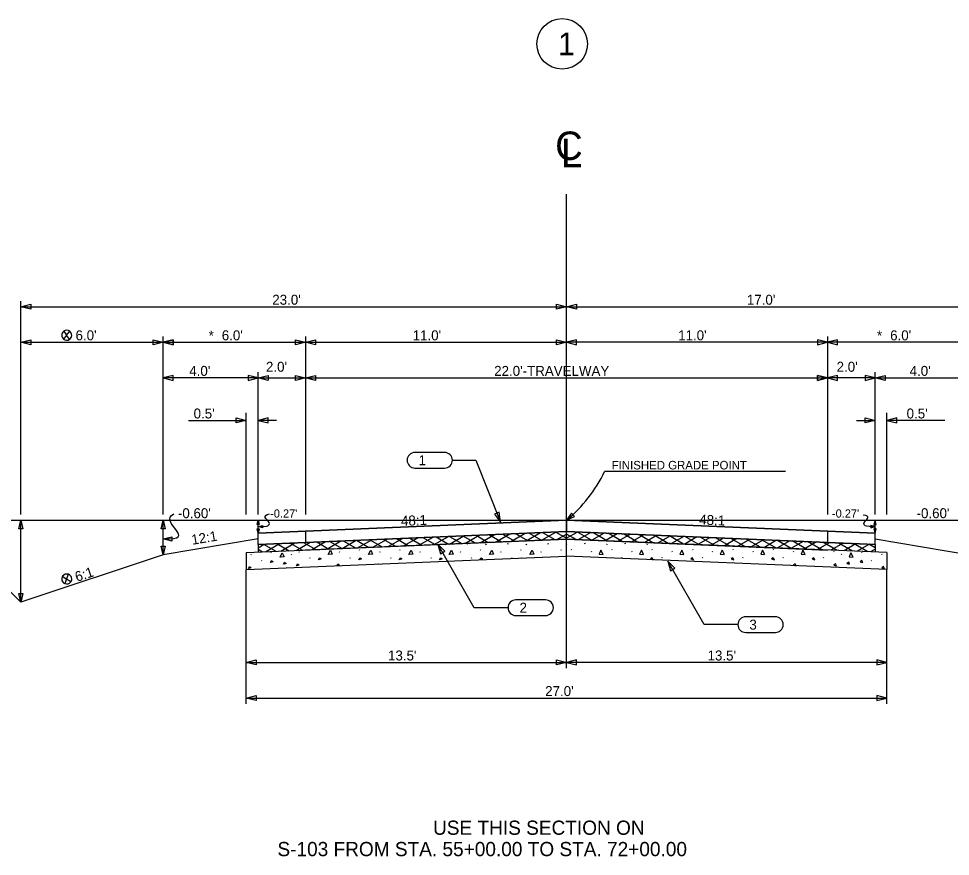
# Model space of a CAD drawing. Extents: x -859 to 797, y 1810 to 2851.
# Drawn here: x -418 to 236, y 2095 to 2684 of the extents above; entities that cross this region are included whole.
import ezdxf

# ---------------------------------------------------------------- set-up
doc = ezdxf.new("R2010")
doc.units = 0
doc.layers.add('Level 41', color=7, linetype='Continuous')

msp = doc.modelspace()

# ---------------------------------------------------------------- linework, layer by layer
at = {"layer": 'Level 41'}
for p, q in [((-33.31, 2227.73), (-33.31, 2560.73)), ((-416.65, 2335.73), (-416.65, 2485.73)), ((-416.65, 2481.73), (-33.31, 2481.73)), ((-33.31, 2481.73), (250.03, 2481.73)), ((-384.48, 2461.69), (-386.63, 2459)), ((-386.52, 2464.46), (-384.48, 2461.69)), ((-384.48, 2461.69), (-382.26, 2464.46)), ((-382.38, 2458.82), (-384.48, 2461.69)), ((-316.65, 2335.73), (-316.65, 2460.73)), ((-216.65, 2460.73), (-216.65, 2335.73)), ((150.03, 2460.73), (150.03, 2335.73)), ((-416.65, 2456.73), (-316.65, 2456.73)), ((-316.65, 2456.73), (-216.65, 2456.73)), ((-216.65, 2456.73), (-33.31, 2456.73)), ((150.03, 2456.73), (-33.31, 2456.73)), ((250.03, 2456.73), (150.03, 2456.73)), ((-249.98, 2335.73), (-249.98, 2435.73)), ((183.36, 2335.73), (183.36, 2435.73)), ((-249.98, 2431.73), (-316.65, 2431.73)), ((-249.98, 2431.73), (-216.65, 2431.73)), ((-216.65, 2431.73), (150.03, 2431.73)), ((183.36, 2431.73), (150.03, 2431.73)), ((183.36, 2431.73), (250.03, 2431.73)), ((-298.96, 2401.8), (-258.32, 2401.8)), ((-258.32, 2335.73), (-258.32, 2407.24)), ((-236.96, 2401.8), (-249.98, 2401.8)), ((170.34, 2401.8), (183.36, 2401.8)), ((191.7, 2335.73), (191.7, 2407.24)), ((232.35, 2401.8), (191.7, 2401.8)), ((-533.89, 2391.32), (-416.65, 2274.09)), ((-119.01, 2379.35), (-139.84, 2379.35)), ((-139.84, 2368.35), (-119.01, 2368.35)), ((120.47, 2365.88), (-6.65, 2365.88)), ((-554.3, 2331.73), (338.21, 2331.73)), ((-416.65, 2274.09), (-416.65, 2331.73)), ((-316.65, 2307.42), (-316.65, 2331.73)), ((-33.31, 2331.73), (-249.98, 2322.7)), ((-249.98, 2322.7), (-249.98, 2331.73)), ((-33.31, 2331.73), (-33.31, 2323.73)), ((-33.31, 2331.73), (183.36, 2322.7)), ((-33.31, 2331.73), (-33.31, 2323.73)), ((183.36, 2322.7), (183.36, 2331.73)), ((-249.98, 2314.7), (-33.3, 2323.73)), ((-216.63, 2324.1), (-216.63, 2316.09)), ((-50.84, 2317.66), (-40.89, 2323.41)), ((-40.94, 2323.41), (-33.31, 2319)), ((183.36, 2314.7), (-33.32, 2323.73)), ((-25.68, 2323.41), (-33.31, 2319)), ((-15.78, 2317.66), (-25.73, 2323.41)), ((150.01, 2324.1), (150.01, 2316.09)), ((-249.98, 2318.53), (-316.65, 2307.42)), ((-258.32, 2309.02), (-33.3, 2318.39)), ((-33.3, 2318.39), (-216.64, 2310.75)), ((-201.73, 2311.37), (-191.78, 2317.12)), ((-199.49, 2316.8), (-190.88, 2311.83)), ((-190.96, 2311.82), (-181, 2317.57)), ((-190.17, 2317.19), (-181.55, 2312.22)), ((-180.84, 2317.58), (-172.23, 2312.6)), ((-180.18, 2312.27), (-170.22, 2318.02)), ((-171.51, 2317.97), (-162.9, 2312.99)), ((-169.4, 2312.72), (-159.44, 2318.47)), ((-162.19, 2318.36), (-153.57, 2313.38)), ((-158.62, 2313.17), (-148.67, 2318.92)), ((-152.86, 2318.74), (-144.24, 2313.77)), ((-147.84, 2313.62), (-137.89, 2319.37)), ((-143.53, 2319.13), (-134.92, 2314.16)), ((-137.07, 2314.07), (-127.11, 2319.82)), ((-134.21, 2319.52), (-125.59, 2314.55)), ((-126.29, 2314.52), (-116.33, 2320.27)), ((-124.88, 2319.91), (-116.26, 2314.94)), ((-115.55, 2320.3), (-106.94, 2315.32)), ((-115.51, 2314.97), (-105.55, 2320.72)), ((-106.23, 2320.69), (-97.61, 2315.71)), ((-104.73, 2315.42), (-94.78, 2321.16)), ((-96.9, 2321.08), (-88.28, 2316.1)), ((-93.95, 2315.86), (-84, 2321.61)), ((-87.57, 2321.46), (-78.96, 2316.49)), ((-83.18, 2316.31), (-73.22, 2322.06)), ((-78.25, 2321.85), (-69.63, 2316.88)), ((-72.4, 2316.76), (-62.44, 2322.51)), ((-68.92, 2322.24), (-60.3, 2317.27)), ((-61.62, 2317.21), (-51.67, 2322.96)), ((-59.59, 2322.63), (-50.98, 2317.66)), ((-50.26, 2323.02), (-41.65, 2318.04)), ((-40.07, 2318.11), (-33.31, 2322.01)), ((191.7, 2309.02), (-33.32, 2318.39)), ((-33.32, 2318.39), (150.02, 2310.75)), ((-26.55, 2318.11), (-33.31, 2322.01)), ((-16.35, 2323.02), (-24.97, 2318.04)), ((-7.03, 2322.63), (-15.64, 2317.66)), ((-5, 2317.21), (-14.95, 2322.96)), ((2.3, 2322.24), (-6.32, 2317.27)), ((5.78, 2316.76), (-4.18, 2322.51)), ((11.63, 2321.85), (3.01, 2316.88)), ((16.56, 2316.31), (6.6, 2322.06)), ((20.95, 2321.46), (12.34, 2316.49)), ((27.34, 2315.86), (17.38, 2321.61)), ((30.28, 2321.08), (21.66, 2316.1)), ((38.11, 2315.42), (28.16, 2321.16)), ((39.61, 2320.69), (30.99, 2315.71)), ((48.89, 2314.97), (38.94, 2320.72)), ((48.93, 2320.3), (40.32, 2315.32)), ((58.26, 2319.91), (49.64, 2314.94)), ((59.67, 2314.52), (49.71, 2320.27)), ((67.59, 2319.52), (58.97, 2314.55)), ((70.45, 2314.07), (60.49, 2319.82)), ((76.91, 2319.13), (68.3, 2314.16)), ((81.22, 2313.62), (71.27, 2319.37)), ((86.24, 2318.74), (77.63, 2313.77)), ((92, 2313.17), (82.05, 2318.92)), ((95.57, 2318.36), (86.95, 2313.38)), ((102.78, 2312.72), (92.82, 2318.47)), ((104.9, 2317.97), (96.28, 2312.99)), ((113.56, 2312.27), (103.6, 2318.02)), ((114.22, 2317.58), (105.61, 2312.6)), ((124.34, 2311.82), (114.38, 2317.57)), ((123.55, 2317.19), (114.93, 2312.22)), ((132.88, 2316.8), (124.26, 2311.83)), ((135.11, 2311.37), (125.16, 2317.12)), ((183.36, 2318.53), (250.03, 2307.42)), ((-249.98, 2312.39), (-245.67, 2314.88)), ((-249.98, 2314.7), (-249.98, 2309.36)), ((-249.98, 2311.31), (-246.84, 2309.49)), ((-246.13, 2314.86), (-237.51, 2309.88)), ((-244.84, 2309.58), (-234.89, 2315.33)), ((-236.8, 2315.25), (-228.19, 2310.27)), ((-234.07, 2310.03), (-224.11, 2315.78)), ((-227.48, 2315.64), (-218.86, 2310.66)), ((-223.29, 2310.48), (-213.33, 2316.22)), ((-218.15, 2316.02), (-209.53, 2311.05)), ((-212.51, 2310.93), (-202.55, 2316.67)), ((-208.82, 2316.41), (-200.21, 2311.44)), ((-207.18, 2310.55), (-206.94, 2311.08)), ((-178.82, 2310.55), (-178.58, 2311.08)), ((-150.46, 2310.55), (-150.22, 2311.08)), ((-122.1, 2310.55), (-121.86, 2311.08)), ((-118.54, 2314.84), (-118.37, 2314.58)), ((-118.37, 2314.8), (-118.13, 2314.45)), ((-102.98, 2314.94), (-102.74, 2315.47)), ((-93.74, 2310.55), (-93.51, 2311.08)), ((-90.25, 2314.94), (-90.01, 2314.58)), ((-90.01, 2314.8), (-89.78, 2314.45)), ((-74.62, 2314.94), (-74.38, 2315.47)), ((-65.38, 2310.55), (-65.15, 2311.08)), ((-61.89, 2314.94), (-61.65, 2314.58)), ((-61.65, 2314.8), (-61.42, 2314.45)), ((-46.26, 2314.94), (-46.03, 2315.47)), ((-37.03, 2310.55), (-36.79, 2311.08)), ((-33.53, 2314.94), (-33.3, 2314.58)), ((-33.09, 2314.94), (-33.32, 2314.58)), ((-29.59, 2310.55), (-29.83, 2311.08)), ((-20.36, 2314.94), (-20.59, 2315.47)), ((-4.96, 2314.8), (-5.2, 2314.45)), ((-4.73, 2314.94), (-4.96, 2314.58)), ((-1.23, 2310.55), (-1.47, 2311.08)), ((8, 2314.94), (7.76, 2315.47)), ((23.39, 2314.8), (23.16, 2314.45)), ((23.63, 2314.94), (23.39, 2314.58)), ((27.12, 2310.55), (26.89, 2311.08)), ((36.36, 2314.94), (36.12, 2315.47)), ((51.75, 2314.8), (51.52, 2314.45)), ((51.93, 2314.84), (51.75, 2314.58)), ((55.48, 2310.55), (55.25, 2311.08)), ((83.84, 2310.55), (83.6, 2311.08)), ((112.2, 2310.55), (111.96, 2311.08)), ((142.2, 2316.41), (133.59, 2311.44)), ((145.89, 2310.93), (135.94, 2316.67)), ((140.56, 2310.55), (140.32, 2311.08)), ((151.53, 2316.02), (142.91, 2311.05)), ((156.67, 2310.48), (146.71, 2316.22)), ((160.86, 2315.64), (152.24, 2310.66)), ((167.45, 2310.03), (157.49, 2315.78)), ((170.18, 2315.25), (161.57, 2310.27)), ((178.23, 2309.58), (168.27, 2315.33)), ((179.51, 2314.86), (170.89, 2309.88)), ((183.36, 2312.39), (179.05, 2314.88)), ((183.36, 2311.31), (180.22, 2309.49)), ((183.36, 2314.7), (183.36, 2309.36)), ((-316.65, 2307.42), (-416.65, 2274.09)), ((-258.32, 2309.02), (-258.32, 2297.02)), ((-258.32, 2297.02), (-33.3, 2306.39)), ((-254.95, 2307.29), (-254.72, 2307.83)), ((-240.92, 2308.66), (-240.69, 2309.19)), ((-226.6, 2307.29), (-226.36, 2307.83)), ((-221.21, 2309.19), (-220.97, 2309.72)), ((-213.81, 2305.4), (-213.57, 2305.04)), ((-192.85, 2309.19), (-192.61, 2309.72)), ((-185.45, 2305.4), (-185.21, 2305.04)), ((-164.49, 2309.19), (-164.25, 2309.72)), ((-157.09, 2305.4), (-156.85, 2305.04)), ((-136.13, 2309.19), (-135.9, 2309.72)), ((-128.73, 2305.4), (-128.5, 2305.04)), ((-107.77, 2309.19), (-107.54, 2309.72)), ((-100.37, 2305.4), (-100.14, 2305.04)), ((-79.42, 2309.19), (-79.18, 2309.72)), ((-72.02, 2305.4), (-71.78, 2305.04)), ((-51.06, 2309.19), (-50.82, 2309.72)), ((191.7, 2297.02), (-33.32, 2306.39)), ((-15.56, 2309.19), (-15.8, 2309.72)), ((5.4, 2305.4), (5.16, 2305.04)), ((12.8, 2309.19), (12.56, 2309.72)), ((33.75, 2305.4), (33.52, 2305.04)), ((41.15, 2309.19), (40.92, 2309.72)), ((62.11, 2305.4), (61.88, 2305.04)), ((69.51, 2309.19), (69.28, 2309.72)), ((90.47, 2305.4), (90.23, 2305.04)), ((97.87, 2309.19), (97.63, 2309.72)), ((118.83, 2305.4), (118.59, 2305.04)), ((126.23, 2309.19), (125.99, 2309.72)), ((147.19, 2305.4), (146.95, 2305.04)), ((154.59, 2309.19), (154.35, 2309.72)), ((159.98, 2307.29), (159.74, 2307.83)), ((174.3, 2308.66), (174.07, 2309.19)), ((188.33, 2307.29), (188.1, 2307.83)), ((191.7, 2309.02), (191.7, 2297.02)), ((-247.55, 2303.5), (-247.32, 2303.15)), ((180.93, 2303.5), (180.7, 2303.15)), ((-387.29, 2292.33), (-384.48, 2290.35)), ((-384.48, 2290.35), (-383.25, 2293.68)), ((-258.32, 2202.73), (-258.32, 2297.02)), ((191.7, 2202.73), (191.7, 2297.02)), ((-384.48, 2290.35), (-385.67, 2287.12)), ((-381.58, 2288.3), (-384.48, 2290.35)), ((-48.12, 2275.72), (-68.96, 2275.72)), ((-68.96, 2264.72), (-48.12, 2264.72)), ((113.31, 2263.82), (92.48, 2263.82)), ((92.48, 2252.82), (113.31, 2252.82)), ((-258.32, 2231.73), (-33.31, 2231.73)), ((191.7, 2231.73), (-33.31, 2231.73)), ((-258.32, 2206.73), (191.7, 2206.73))]:
    msp.add_line(p, q, dxfattribs=at)
for points in [[(-409.65, 2479.98), (-416.65, 2481.73), (-409.65, 2483.48)], [(-40.31, 2483.48), (-33.31, 2481.73), (-40.31, 2479.98)], [(-26.31, 2479.98), (-33.31, 2481.73), (-26.31, 2483.48)], [(-409.65, 2454.98), (-416.65, 2456.73), (-409.65, 2458.48)], [(-323.65, 2458.48), (-316.65, 2456.73), (-323.65, 2454.98)], [(-309.65, 2458.48), (-316.65, 2456.73), (-309.65, 2454.98)], [(-309.65, 2454.98), (-316.65, 2456.73), (-309.65, 2458.48)], [(-223.65, 2458.48), (-216.65, 2456.73), (-223.65, 2454.98)], [(-209.65, 2454.98), (-216.65, 2456.73), (-209.65, 2458.48)], [(-40.31, 2458.48), (-33.31, 2456.73), (-40.31, 2454.98)], [(-26.31, 2458.48), (-33.31, 2456.73), (-26.31, 2454.98)], [(143.03, 2454.98), (150.03, 2456.73), (143.03, 2458.48)], [(157.03, 2458.48), (150.03, 2456.73), (157.03, 2454.98)], [(-309.65, 2433.48), (-316.65, 2431.73), (-309.65, 2429.98)], [(-256.98, 2429.98), (-249.98, 2431.73), (-256.98, 2433.48)], [(-242.98, 2429.98), (-249.98, 2431.73), (-242.98, 2433.48)], [(-223.65, 2433.48), (-216.65, 2431.73), (-223.65, 2429.98)], [(-209.65, 2429.98), (-216.65, 2431.73), (-209.65, 2433.48)], [(143.03, 2433.48), (150.03, 2431.73), (143.03, 2429.98)], [(143.03, 2429.98), (150.03, 2431.73), (143.03, 2433.48)], [(157.03, 2433.48), (150.03, 2431.73), (157.03, 2429.98)], [(176.36, 2429.98), (183.36, 2431.73), (176.36, 2433.48)], [(190.36, 2429.98), (183.36, 2431.73), (190.36, 2433.48)], [(-265.32, 2403.55), (-258.32, 2401.8), (-265.32, 2400.05)], [(-242.98, 2403.55), (-249.98, 2401.8), (-242.98, 2400.05)], [(176.36, 2403.55), (183.36, 2401.8), (176.36, 2400.05)], [(198.7, 2403.55), (191.7, 2401.8), (198.7, 2400.05)], [(-84.01, 2336.05), (-79.82, 2330.44), (-80.65, 2337.4)], [(-29.84, 2336.62), (-33.31, 2331.73), (-27.86, 2334.23)], [(-418.15, 2325.73), (-416.65, 2331.73), (-415.15, 2325.73)], [(-318.15, 2325.73), (-316.65, 2331.73), (-315.15, 2325.73)], [(-250.73, 2328.73), (-249.98, 2331.73), (-249.23, 2328.73)], [(-249.98, 2322.7), (-33.31, 2331.73), (-33.31, 2331.73), (-33.31, 2323.73), (-33.31, 2323.73), (-249.98, 2314.7)], [(183.36, 2322.7), (-33.31, 2331.73), (-33.31, 2331.73), (-33.31, 2323.73), (-33.31, 2323.73), (183.36, 2314.7)], [(184.11, 2328.73), (183.36, 2331.73), (182.61, 2328.73)], [(-249.23, 2325.7), (-249.98, 2322.7), (-250.73, 2325.7)], [(-246.98, 2326.44), (-249.98, 2327.18), (-246.98, 2327.94)], [(180.36, 2326.44), (183.36, 2327.18), (180.36, 2327.94)], [(182.61, 2325.7), (183.36, 2322.7), (184.11, 2325.7)], [(-310.66, 2316.96), (-316.65, 2318.5), (-310.64, 2319.96)], [(-315.15, 2313.42), (-316.65, 2307.42), (-318.15, 2313.42)], [(-118.73, 2309.89), (-123.65, 2314.87), (-121.88, 2308.1)], [(42.71, 2297.99), (37.79, 2302.96), (39.56, 2296.19)], [(-415.15, 2280.09), (-416.65, 2274.09), (-418.15, 2280.09)], [(-251.32, 2229.98), (-258.32, 2231.73), (-251.32, 2233.48)], [(-40.31, 2233.48), (-33.31, 2231.73), (-40.31, 2229.98)], [(-26.31, 2233.48), (-33.31, 2231.73), (-26.31, 2229.98)], [(184.7, 2229.98), (191.7, 2231.73), (184.7, 2233.48)], [(-251.32, 2204.98), (-258.32, 2206.73), (-251.32, 2208.48)], [(184.7, 2204.98), (191.7, 2206.73), (184.7, 2208.48)]]:
    msp.add_lwpolyline(points, close=True, dxfattribs=at)
for points in [[(-113.51, 2373.85), (-97.17, 2373.85), (-79.82, 2330.44)], [(-200.84, 2307.59), (-199.24, 2310.61), (-198, 2307.82), (-200.78, 2307.59)], [(-172.48, 2307.59), (-170.88, 2310.61), (-169.64, 2307.82), (-172.42, 2307.59)], [(-144.12, 2307.59), (-142.53, 2310.61), (-141.28, 2307.82), (-144.07, 2307.59)], [(-74.46, 2270.22), (-98.23, 2270.22), (-123.65, 2314.87)], [(-115.77, 2307.59), (-114.17, 2310.61), (-112.92, 2307.82), (-115.71, 2307.59)], [(-87.41, 2307.59), (-85.81, 2310.61), (-84.57, 2307.82), (-87.35, 2307.59)], [(-59.05, 2307.59), (-57.45, 2310.61), (-56.21, 2307.82), (-58.99, 2307.59)], [(-7.57, 2307.59), (-9.17, 2310.61), (-10.41, 2307.82), (-7.63, 2307.59)], [(20.79, 2307.59), (19.19, 2310.61), (17.95, 2307.82), (20.73, 2307.59)], [(49.15, 2307.59), (47.55, 2310.61), (46.31, 2307.82), (49.09, 2307.59)], [(77.51, 2307.59), (75.91, 2310.61), (74.66, 2307.82), (77.45, 2307.59)], [(105.86, 2307.59), (104.27, 2310.61), (103.02, 2307.82), (105.8, 2307.59)], [(134.22, 2307.59), (132.62, 2310.61), (131.38, 2307.82), (134.16, 2307.59)], [(-234.59, 2305.7), (-232.99, 2308.71), (-231.75, 2305.93), (-234.53, 2305.7)], [(-207.59, 2303.86), (-206.88, 2305.34), (-205.7, 2304.45), (-207.59, 2303.86)], [(-179.23, 2303.86), (-178.52, 2305.34), (-177.34, 2304.45), (-179.23, 2303.86)], [(-150.87, 2303.86), (-150.16, 2305.34), (-148.98, 2304.45), (-150.87, 2303.86)], [(-122.52, 2303.86), (-121.81, 2305.34), (-120.62, 2304.45), (-122.52, 2303.86)], [(-94.16, 2303.86), (-93.45, 2305.34), (-92.26, 2304.45), (-94.16, 2303.86)], [(-65.22, 2305.06), (-65.09, 2305.34), (-64.75, 2305.08)], [(-1.4, 2305.06), (-1.53, 2305.34), (-1.87, 2305.08)], [(27.54, 2303.86), (26.83, 2305.34), (25.64, 2304.45), (27.54, 2303.86)], [(55.9, 2303.86), (55.19, 2305.34), (54, 2304.45), (55.9, 2303.86)], [(84.26, 2303.86), (83.54, 2305.34), (82.36, 2304.45), (84.26, 2303.86)], [(112.61, 2303.86), (111.9, 2305.34), (110.72, 2304.45), (112.61, 2303.86)], [(140.97, 2303.86), (140.26, 2305.34), (139.08, 2304.45), (140.97, 2303.86)], [(167.97, 2305.7), (166.37, 2308.71), (165.13, 2305.93), (167.91, 2305.7)], [(-256.72, 2297.73), (-256.01, 2299.21), (-254.82, 2298.33), (-256.72, 2297.73)], [(-241.34, 2301.97), (-240.63, 2303.45), (-239.44, 2302.56), (-241.34, 2301.97)], [(-232.12, 2300.78), (-231.43, 2302.21), (-230.25, 2301.32), (-231.98, 2300.78)], [(-222.97, 2299.63), (-222.26, 2301.11), (-221.08, 2300.22), (-222.97, 2299.63)], [(-194.59, 2299.67), (-193.9, 2301.11), (-192.72, 2300.22), (-194.45, 2299.68)], [(-165.65, 2300.88), (-165.54, 2301.11), (-165.26, 2300.89)], [(86.98, 2258.32), (63.21, 2258.32), (37.79, 2302.96)], [(99.04, 2300.88), (98.93, 2301.11), (98.64, 2300.89)], [(127.97, 2299.67), (127.28, 2301.11), (126.1, 2300.22), (127.83, 2299.68)], [(156.35, 2299.63), (155.64, 2301.11), (154.46, 2300.22), (156.35, 2299.63)], [(165.5, 2300.78), (164.82, 2302.21), (163.63, 2301.32), (165.36, 2300.78)], [(174.72, 2301.97), (174.01, 2303.45), (172.82, 2302.56), (174.72, 2301.97)], [(190.1, 2297.73), (189.39, 2299.21), (188.2, 2298.33), (190.1, 2297.73)]]:
    msp.add_lwpolyline(points, dxfattribs=at)
msp.add_circle((-36.42, 2666.43), 17.76, dxfattribs=at)
for centre, radius, start, end in [((-384.39, 2461.68), 3.5, 127.56717, 230.12148), ((-384.39, 2461.68), 3.5, 52.52735, 127.56717), ((-384.39, 2461.68), 3.5, 305.1618, 52.52735), ((-384.39, 2461.68), 3.5, 230.12148, 305.1618), ((-139.84, 2373.85), 5.5, 90, 270), ((-119.01, 2373.85), 5.5, 270, 90), ((-98.03, 2409.74), 101.37, 309.68079, 334.36101), ((-384.39, 2290.38), 3.5, 146.00207, 248.55638), ((-384.39, 2290.38), 3.5, 70.96225, 146.00207), ((-384.39, 2290.38), 3.5, 323.5967, 70.96225), ((-384.39, 2290.38), 3.5, 248.55638, 323.5967), ((-68.96, 2270.22), 5.5, 90, 270), ((-48.12, 2270.22), 5.5, 270, 90), ((92.48, 2258.32), 5.5, 90, 270), ((113.31, 2258.32), 5.5, 270, 90)]:
    msp.add_arc(centre, radius, start, end, dxfattribs=at)
for points in [[(-316.65, 2318.5), (-303.94, 2318.42), (-305.29, 2322.98), (-315.05, 2333.69), (-309.13, 2336.15)], [(-249.98, 2327.18), (-243.52, 2327.19), (-242.68, 2327.84), (-241.05, 2330.59), (-247.45, 2334.6), (-241.94, 2336.26)], [(183.36, 2327.18), (176.91, 2327.19), (176.06, 2327.84), (174.43, 2330.59), (180.83, 2334.6), (175.08, 2335.33)]]:
    msp.add_open_spline(points, degree=3, dxfattribs=at)

# ---------------------------------------------------------------- texts
for s, height, p in [('1', 16, (-39.4, 2658.43)), ('C', 20, (-41.32, 2584.84)), ('L', 20, (-37.21, 2579.74)), ("23.0'", 7, (-240.03, 2483.13)), ("17.0'", 7, (93.31, 2483.13)), ("6.0'", 7, (-378.22, 2458.13)), ('*', 7, (-284.74, 2457.9)), ("6.0'", 7, (-275.5, 2458.13)), ("11.0'", 7, (-141.43, 2458.13)), ("11.0'", 7, (45.05, 2458.13)), ('*', 7, (184.71, 2457.9)), ("6.0'", 7, (193.96, 2458.13)), ("2.0'", 7, (-244.46, 2436.03)), ("2.0'", 7, (156.35, 2436.03)), ("4.0'", 7, (-298.34, 2433.13)), ("22.0'-TRAVELWAY", 7, (-84.18, 2433.13)), ("4.0'", 7, (207.63, 2433.13)), ("0.5'", 7, (-295.29, 2403.2)), ("0.5'", 7, (205.52, 2403.2)), ('FINISHED GRADE POINT', 6, (-1.65, 2367.38)), ("-0.60'", 7, (-306.3, 2333.13)), ("-0.27'", 5.775, (-241.53, 2333.53)), ("-0.27'", 5.775, (153.1, 2333.53)), ("-0.60'", 7, (212.52, 2333.13)), ("13.5'", 7, (-158.74, 2233.13)), ("13.5'", 7, (65.7, 2233.13)), ("27.0'", 7, (-48.36, 2208.13)), ('USE THIS SECTION ON', 10, (-127.11, 2110.61)), ('S-103 FROM STA. 55+00.00 TO STA. 72+00.00', 10, (-236.4, 2095.61))]:
    msp.add_text(s, height=height, dxfattribs=at).set_placement(p)
for s, rotation, p in [(' 1 ', 360, (-139.84, 2370.35)), ('48:1', 2.38587, (-149.48, 2327.69)), ('48:1', 357.61413, (59.74, 2328.66)), ('12:1', 9.46232, (-296.22, 2314.4)), ('6:1', 18.43495, (-377.23, 2288.33)), (' 2 ', 360, (-68.96, 2266.72)), (' 3 ', 360, (92.48, 2254.82))]:
    msp.add_text(s, height=7, rotation=rotation, dxfattribs=at).set_placement(p)

doc.saveas('drawing.dxf')
